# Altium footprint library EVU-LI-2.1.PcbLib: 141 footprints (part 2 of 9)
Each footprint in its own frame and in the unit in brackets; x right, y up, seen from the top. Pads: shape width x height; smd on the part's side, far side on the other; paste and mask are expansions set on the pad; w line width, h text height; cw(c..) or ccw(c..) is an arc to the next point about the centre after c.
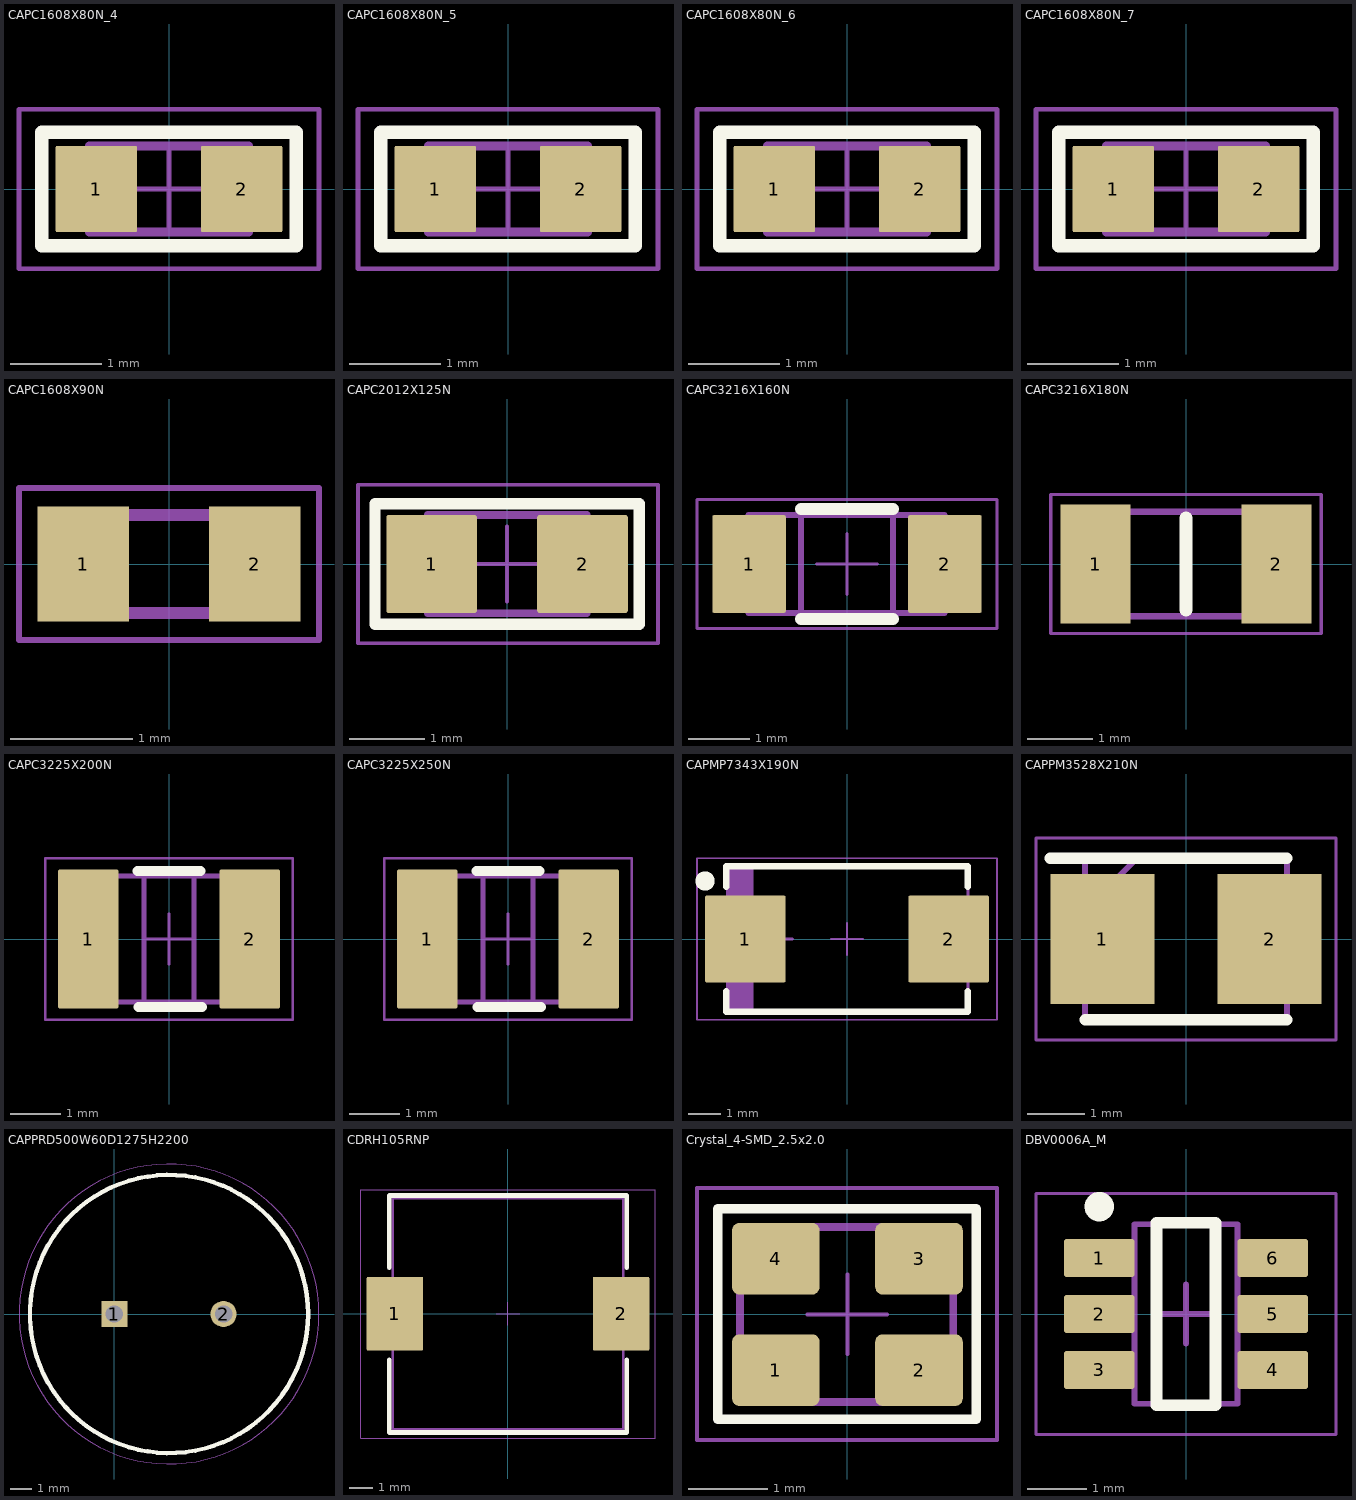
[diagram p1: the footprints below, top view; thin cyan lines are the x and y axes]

## CAPC1608X80N_4 [mm]
pads (2):
  rrect5% 0.9x0.95 smd mask+0.07: 1(-0.8,0) 2(0.8,0)
Top Overlay:
  lines w0.15: -1.4,-0.625 -1.4,0.625 1.4,0.625 1.4,-0.625 -1.4,-0.625
Top Assembly:
  lines w0.1: -0.875,-0.475 -0.875,0.475 0.875,0.475 0.875,-0.475 -0.875,-0.475
Top Designator:
  text ".Designator" at -3.25,-0.3 h1.5
Top Courtyard:
  lines w0.05: -0.5,0 0.5,0 ; 0,-0.5 0,0.5 ; -1.65,-0.875 -1.65,0.875 1.65,0.875 1.65,-0.875 -1.65,-0.875
3D body "0603c.STEP": height 0.85, standoff 0, extent -0.875,-0.475 0.875,0.475

## CAPC1608X80N_5 [mm]
pads (2):
  rrect5% 0.9x0.95 smd mask+0.07: 1(-0.8,0) 2(0.8,0)
Top Overlay:
  lines w0.15: -1.4,-0.625 1.4,-0.625 1.4,0.625 -1.4,0.625 -1.4,-0.625
Top Assembly:
  lines w0.1: -0.875,-0.475 0.875,-0.475 0.875,0.475 -0.875,0.475 -0.875,-0.475
Top Courtyard:
  lines w0.05: -0.5,0 0.5,0 ; 0,-0.5 0,0.5 ; -1.65,-0.875 1.65,-0.875 1.65,0.875 -1.65,0.875 -1.65,-0.875
3D body "0603c.STEP": height 0.85, standoff 0, extent -0.875,-0.475 0.875,0.475

## CAPC1608X80N_6 [mm]
pads (2):
  rrect5% 0.9x0.95 smd mask+0.07: 1(-0.8,0) 2(0.8,0)
Top Overlay:
  lines w0.15: -1.4,-0.625 -1.4,0.625 1.4,0.625 1.4,-0.625 -1.4,-0.625
Top Assembly:
  lines w0.1: -0.875,-0.475 -0.875,0.475 0.875,0.475 0.875,-0.475 -0.875,-0.475
Top Courtyard:
  lines w0.05: -0.5,0 0.5,0 ; 0,-0.5 0,0.5 ; -1.65,-0.875 -1.65,0.875 1.65,0.875 1.65,-0.875 -1.65,-0.875
3D body "0603c.STEP": height 0.85, standoff 0, extent -0.875,-0.475 0.875,0.475

## CAPC1608X80N_7 [mm]
pads (2):
  rrect5% 0.9x0.95 smd mask+0.07: 1(-0.8,0) 2(0.8,0)
Top Overlay:
  lines w0.15: -1.4,-0.625 -1.4,0.625 1.4,0.625 1.4,-0.625 -1.4,-0.625
Top Assembly:
  lines w0.1: -0.875,-0.475 -0.875,0.475 0.875,0.475 0.875,-0.475 -0.875,-0.475
Top Courtyard:
  lines w0.05: -0.5,0 0.5,0 ; 0,-0.5 0,0.5 ; -1.65,-0.875 -1.65,0.875 1.65,0.875 1.65,-0.875 -1.65,-0.875
3D body "0603c.STEP": height 0.85, standoff 0, extent -0.875,-0.475 0.875,0.475

## CAPC1608X90N [mm]
pads (2):
  rect 0.75x0.94 smd: 1(-0.7,0) 2(0.7,0)
Mechanical 13:
  lines w0.1: -0.8,-0.4 0.8,-0.4 0.8,0.4 -0.8,0.4 -0.8,-0.4
Top Courtyard:
  lines w0.05: -1.225,-0.62 1.225,-0.62 1.225,0.62 -1.225,0.62 -1.225,-0.62
3D body "GRM188R72A102JA01D.stp": height 0.8, standoff 0, extent -0.8,-0.45 0.8,0.45

## CAPC2012X125N [mm]
pads (2):
  rrect5% 1.2x1.3 smd mask+0.07: 1(-1,0) 2(1,0)
Top Overlay:
  lines w0.15: -1.75,-0.8 1.75,-0.8 1.75,0.8 -1.75,0.8 -1.75,-0.8
Top Assembly:
  lines w0.1: -0.697,-0.651 -0.697,0.649 ; 0.703,-0.651 0.703,0.649 ; -1.05,-0.651 -1.05,0.649 1.053,0.649 1.053,-0.651 -1.05,-0.651
Top Designator:
  text ".Designator" at -3.25,-0.3 h1.5
Top Courtyard:
  lines w0.05: -0.5,0 0.5,0 ; 0,-0.5 0,0.5 ; -1.975,-1.05 2,-1.05 2,1.05 -1.975,1.05 -1.975,-1.05
3D body: height 1.25, standoff 0, extent 0.4,-0.65 1.05,0.65
3D body: height 1.25, standoff 0, extent -1.05,-0.65 -0.4,0.65
3D body: height 1.2, standoff 0, extent -0.4,-0.6 0.4,0.6

## CAPC3216X160N [mm]
pads (2):
  rrect5% 1.2x1.6 smd mask+0.07: 1(-1.6,0) 2(1.6,0)
Top Overlay:
  lines w0.2: -0.75,-0.9 0.75,-0.9 ; -0.75,0.9 0.75,0.9
Top Assembly:
  lines w0.1: -0.75,-0.799 -0.75,0.801 ; 0.75,-0.799 0.75,0.801 ; -1.605,-0.799 -1.605,0.801 1.595,0.801 1.595,-0.799 -1.605,-0.799
Top Designator:
  text ".Designator" at -3.25,-0.3 h1.5
Top Courtyard:
  lines w0.05: -0.5,0 0.5,0 ; 0,-0.5 0,0.5 ; -2.45,-1.05 -2.45,1.05 2.45,1.05 2.45,-1.05 -2.45,-1.05
3D body: height 1.6, standoff 0, extent 0.75,-0.8 1.55,0.8
3D body: height 1.6, standoff 0, extent -1.55,-0.8 -0.75,0.8
3D body: height 1.55, standoff 0, extent -0.75,-0.75 0.75,0.75

## CAPC3216X180N [mm]
pads (2):
  rect 1.07x1.82 smd: 1(-1.38,0) 2(1.38,0)
Top Overlay:
  lines w0.2: 0,-0.7 0,0.7
Mechanical 13:
  lines w0.1: -1.6,-0.8 1.6,-0.8 1.6,0.8 -1.6,0.8 -1.6,-0.8
Top Courtyard:
  lines w0.05: -2.065,-1.06 2.065,-1.06 2.065,1.06 -2.065,1.06 -2.065,-1.06
3D body "GRM31CR61H106KA12L.stp": height 1.8, standoff 0, extent -1.6,-0.8 1.6,0.8

## CAPC3225X200N [mm]
pads (2):
  rrect5% 1.2x2.75 smd mask+0.07: 1(-1.6,0) 2(1.6,0)
Top Overlay:
  lines w0.2: -0.625,1.35 0.625,1.35 ; -0.6,-1.35 0.65,-1.35
Top Assembly:
  lines w0.1: -0.5,-1.25 -0.5,1.25 ; 0.5,-1.25 0.5,1.25 ; -1.6,-1.25 1.6,-1.25 1.6,1.25 -1.6,1.25 -1.6,-1.25
Top Designator:
  text ".Designator" at -3.25,-0.3 h1.5
Top Courtyard:
  lines w0.05: -0.5,0 0.5,0 ; 0,-0.5 0,0.5 ; -2.45,-1.6 2.45,-1.6 2.45,1.6 -2.45,1.6 -2.45,-1.6
3D body: height 2, standoff 0, extent 0.5,-1.25 1.6,1.25
3D body: height 2, standoff 0, extent -1.6,-1.25 -0.5,1.25
3D body: height 1.95, standoff 0, extent -0.5,-1.2 0.5,1.2

## CAPC3225X250N [mm]
pads (2):
  rrect5% 1.2x2.75 smd mask+0.07: 1(-1.6,0) 2(1.6,0)
Top Overlay:
  lines w0.2: -0.625,1.35 0.625,1.35 ; -0.6,-1.35 0.65,-1.35
Top Assembly:
  lines w0.1: -0.5,-1.25 -0.5,1.25 ; 0.5,-1.25 0.5,1.25 ; -1.6,-1.25 -1.6,1.25 1.6,1.25 1.6,-1.25 -1.6,-1.25
Top Designator:
  text ".Designator" at -3.25,-0.3 h1.5
Top Courtyard:
  lines w0.05: -0.5,0 0.5,0 ; 0,-0.5 0,0.5 ; -2.45,-1.6 -2.45,1.6 2.45,1.6 2.45,-1.6 -2.45,-1.6
3D body: height 2.45, standoff 0, extent -0.5,-1.2 0.5,1.2
3D body: height 2.5, standoff 0, extent -1.6,-1.25 -0.5,1.25
3D body: height 2.5, standoff 0, extent 0.5,-1.25 1.6,1.25

## CAPMP7343X190N [mm]
pads (2):
  rrect5% 2.5x2.7 smd mask+0.07: 1(-3.15,0) 2(3.15,0)
Top Overlay:
  circle w0.3: c-4.4,1.8 r0.15
  lines w0.2: -3.75,-1.625 -3.75,-2.25 3.75,-2.25 3.75,-1.625 ; -3.75,1.625 -3.75,2.25 3.75,2.25 3.75,1.625
Top Assembly:
  region: -3.75,-2.26 -2.9,-2.26 -2.9,2.25 -3.75,2.25
  lines w0.1: -3.7,-2.25 3.75,-2.25 3.75,2.25 -3.7,2.25 ; -2.5,0 -1.7,0 ; -2.1,-0.4 -2.1,0.4
Top Designator:
  text ".Designator" at -3.275,-0.3 h1.5
Mechanical 9:
  text ".MARK" at -1.75,0.675 h1.2
Top Courtyard:
  lines w0.05: -0.5,0 0.5,0 ; 0,-0.5 0,0.5 ; -4.65,-2.5 -4.65,2.5 4.65,2.5 4.65,-2.5 -4.65,-2.5
3D body: height 2.01, standoff 2, extent -3.238,-2.15 -1.875,2.15
3D body: height 2, standoff 0, extent -3.446,-2.3 3.446,2.3

## CAPPM3528X210N [mm]
pads (2):
  rect 1.8x2.25 smd: 1(-1.45,0) 2(1.45,0)
Top Overlay:
  lines w0.2: -2.35,1.4 1.75,1.4 ; -1.75,-1.4 1.75,-1.4
Assembly Notes:
  lines w0.1: -1.75,0.5 -0.85,1.4 ; -1.75,-1.4 1.75,-1.4 1.75,1.4 -1.75,1.4 -1.75,-1.4
Top Courtyard:
  lines w0.05: -2.6,-1.75 2.6,-1.75 2.6,1.75 -2.6,1.75 -2.6,-1.75
3D body "293D106X0020B2TE3.stp": height 2.13, standoff 0, extent -1.864,-1.539 1.87,1.535

## CAPPRD500W60D1275H2200 [mm]
pads (2):
  rect 1.2x1.2 hole 0.8: 1(0,0)
  round 1.2 hole 0.8: 2(5,0)
Top Overlay:
  circle w0.2: c2.5,0 r6.375
Mechanical 13:
  circle w0.1: c2.5,0 r6.375
Top Courtyard:
  circle w0.05: c2.5,0 r6.875
3D body "UPS1J331MHD.stp": height 22, standoff -10, extent -3.988,-6.497 9,6.497

## CDRH105RNP [mm]
pads (2):
  rrect5% 2.45x3.2 smd mask+0.07: 1(-4.9,0) 2(4.9,0)
Top Overlay:
  lines w0.2: -5.15,-2 -5.15,-5.15 5.15,-5.15 5.15,-2 ; -5.15,2 -5.15,5.125 5.15,5.125 5.15,2
Top Assembly:
  lines w0.1: -5,-5 -5,5 5,5 5,-5 -5,-5
Top Designator:
  text ".Designator" at -3.275,-0.3 h1.5
Mechanical 9:
  text ".MARK" at -1.75,0.675 h1.2
Top Courtyard:
  lines w0.05: -0.5,0 0.5,0 ; 0,-0.5 0,0.5 ; -6.375,-5.4 -6.375,5.375 6.375,5.375 6.375,-5.4 -6.375,-5.4
3D body "SDRH105R.STEP": height 5.1, standoff 0, extent -5,-5 5,5

## Crystal_4-SMD_2.5x2.0 [mm]
height 0.5
pads (4):
  rrect20% 1.1x0.9 smd mask+0.075: 1(-0.9,-0.7) 2(0.9,-0.7) 3(0.9,0.7) 4(-0.9,0.7)
Top Overlay:
  lines w0.12: -1.63,-1.32 -1.63,1.33 1.62,1.33 1.62,-1.32 -1.63,-1.32
  text "." at -1.72,-1.77 h4
Top Assembly:
  lines w0.1: -1.35,-1.1 1.33,-1.1 1.33,1.1 -1.35,1.1 -1.35,-1.1
  text "." at -1.14,-0.88 h4
  text ".Designator" at -1.17,0.43 h0.6
Top Value:
  text ".Comment" at -1.24,-0.25 h0.5
Top Courtyard:
  lines w0.05: -0.5,0 0.5,0 ; 0,-0.5 0,0.5 ; -1.89,-1.58 -1.89,1.59 1.88,1.59 1.88,-1.58 -1.89,-1.58
3D body "ABM10_Xtal.step": height 0.7, standoff -0.01, extent -1.3,-1.05 1.3,1.05

## DBV0006A_M [mm] "SOT23, 6-Leads, Body 3.05x1.75mm, Pitch 0.95mm, IPC Low Density"
height 1.45
pads (6):
  rrect15% 1.2x0.65 smd: 1(-1.475,0.95) 2(-1.475,0) 3(-1.475,-0.95) 4(1.475,-0.95) 5(1.475,0) 6(1.475,0.95)
Top Overlay:
  circle w0.25: c-1.475,1.825 r0.125
  lines w0.2: -0.5,-1.55 -0.5,1.55 0.5,1.55 0.5,-1.55 -0.5,-1.55
Mechanical 1:
  text ".Designator" at -0.635,-0.127 h0.4
Mechanical 13:
  lines w0.1: -0.875,-1.525 0.875,-1.525 0.875,1.525 -0.875,1.525 -0.875,-1.525
Top Courtyard:
  lines w0.05: -2.55,-2.05 2.55,-2.05 2.55,2.05 -2.55,2.05 -2.55,-2.05
  lines w0.1: -0.5,0 0.5,0 ; 0,-0.5 0,0.5
3D body "DBV0006AakaMF06A.stp": height 1.11, standoff -0.01, extent -1.422,-1.461 1.422,1.46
